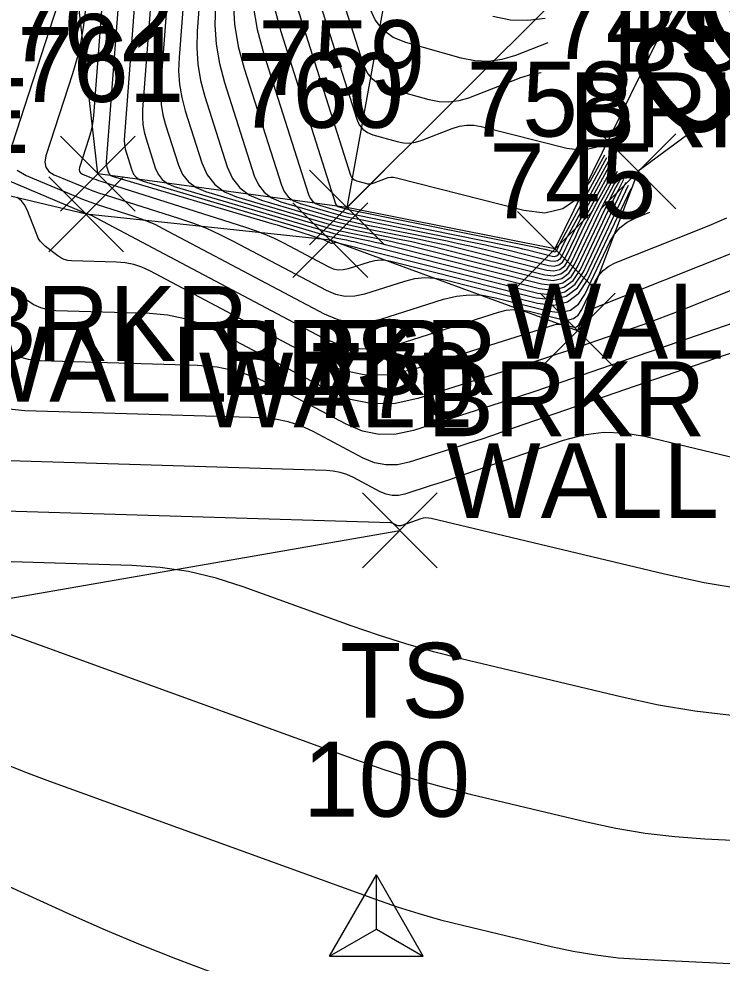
# Model space of a CAD drawing. Extents: x 1650836 to 1652450, y 332578 to 333908.
# Drawn here: x 1652071.34 to 1652090.12, y 332688.37 to 332713.58 of the extents above; entities that cross this region are included whole.
import ezdxf

# ---------------------------------------------------------------- set-up
doc = ezdxf.new("R2010")
doc.units = 0
for name, color, linetype in [('C_I', 7, 'Continuous'), ('CPSM', 7, 'Continuous'), ('L_A', 7, 'Continuous'), ('L_C', 7, 'Continuous'), ('L_I', 7, 'Continuous'), ('L_TIC', 7, 'Continuous'), ('LARO', 7, 'Continuous'), ('LAWE', 7, 'Continuous'), ('LELB', 7, 'Continuous'), ('LSOGCMA', 7, 'Continuous'), ('LSOGCMA_T', 7, 'Continuous'), ('LSOGCMI', 7, 'Continuous'), ('LW', 7, 'Continuous')]:
    doc.layers.add(name, color=color, linetype=linetype)

msp = doc.modelspace()

# ---------------------------------------------------------------- linework, layer by layer
at = {"layer": 'CPSM'}
for p, q in [((1652079.638, 332688.56), (1652080.888, 332690.725)), ((1652082.138, 332688.56), (1652080.888, 332690.725)), ((1652080.888, 332689.281), (1652080.888, 332690.725)), ((1652079.638, 332688.56), (1652080.888, 332689.281)), ((1652080.888, 332689.281), (1652080.888, 332689.281)), ((1652080.888, 332689.281), (1652082.138, 332688.56)), ((1652079.638, 332688.56), (1652082.138, 332688.56))]:
    msp.add_line(p, q, dxfattribs=at)
at = {"layer": 'L_TIC'}
for points in [[(1652072.451, 332708.446), (1652074.451, 332710.446)], [(1652074.451, 332708.446), (1652072.451, 332710.446)], [(1652086.881, 332708.509), (1652088.881, 332710.509)], [(1652088.881, 332708.509), (1652086.881, 332710.509)], [(1652079.101, 332707.542), (1652081.101, 332709.542)], [(1652081.101, 332707.542), (1652079.101, 332709.542)], [(1652079.101, 332707.542), (1652081.101, 332709.542)], [(1652081.101, 332707.542), (1652079.101, 332709.542)], [(1652079.101, 332707.542), (1652081.101, 332709.542)], [(1652081.101, 332707.542), (1652079.101, 332709.542)], [(1652072.141, 332707.362), (1652074.141, 332709.362)], [(1652074.141, 332707.362), (1652072.141, 332709.362)], [(1652078.661, 332706.671), (1652080.661, 332708.671)], [(1652080.661, 332706.671), (1652078.661, 332708.671)], [(1652084.656, 332706.437), (1652086.656, 332708.437)], [(1652086.656, 332706.437), (1652084.656, 332708.437)], [(1652085.261, 332704.252), (1652087.261, 332706.252)], [(1652087.261, 332704.252), (1652085.261, 332706.252)], [(1652080.514, 332698.922), (1652082.514, 332700.922)], [(1652082.514, 332698.922), (1652080.514, 332700.922)]]:
    msp.add_lwpolyline(points, dxfattribs=at)
at = {"layer": 'LARO'}
msp.add_lwpolyline([(1652076.603, 332758.368), (1652078.878, 332757.841), (1652083.698, 332755.279), (1652084.666, 332748.821), (1652086.861, 332729.205), (1652082.01, 332719.071), (1652080.101, 332708.542)], dxfattribs=at)
at = {"layer": 'LAWE'}
msp.add_lwpolyline([(1652113.729, 332729.971), (1652105.001, 332721.607), (1652097.708, 332720.127), (1652089.433, 332715.148), (1652085.656, 332707.437), (1652080.101, 332708.542), (1652073.451, 332709.446), (1652072.158, 332720.813), (1652060.852, 332721.144), (1652052.615, 332711.419), (1652043.802, 332704.554), (1652032.724, 332702.068), (1652025.188, 332702.458), (1652014.024, 332714.079), (1651995.915, 332712.612)], dxfattribs=at)
at = {"layer": 'LELB'}
for points in [[(1652083.698, 332755.279), (1652086.382, 332753.968), (1652097.265, 332747.108), (1652108.096, 332741.456), (1652107.571, 332735.708), (1652094.748, 332723.239), (1652088.748, 332717.173), (1652080.101, 332708.542)], [(1652062.736, 332702.235), (1652067.941, 332697.559), (1652081.514, 332699.922)]]:
    msp.add_lwpolyline(points, dxfattribs=at)
at = {"layer": 'LSOGCMA'}
for points in [[(1652076.593, 332713.944), (1652076.577, 332713.419), (1652076.613, 332712.9), (1652076.698, 332712.387), (1652076.834, 332711.88), (1652077.629, 332709.386), (1652077.737, 332709.144), (1652077.89, 332708.948), (1652078.089, 332708.799), (1652078.334, 332708.696), (1652079.404, 332708.38), (1652079.672, 332708.304), (1652079.942, 332708.234), (1652080.213, 332708.17), (1652080.486, 332708.111), (1652082.779, 332707.649), (1652083.083, 332707.585), (1652083.387, 332707.518), (1652083.69, 332707.448), (1652083.992, 332707.373), (1652085.485, 332706.996), (1652085.632, 332706.979), (1652085.756, 332707.009), (1652085.859, 332707.086), (1652085.94, 332707.21), (1652086.219, 332707.797), (1652086.289, 332707.943), (1652086.362, 332708.088), (1652086.437, 332708.233), (1652086.514, 332708.376), (1652087.215, 332709.661)], [(1652070.785, 332709.383), (1652073.122, 332708.394), (1652073.135, 332708.388), (1652073.147, 332708.384), (1652073.16, 332708.379), (1652073.173, 332708.375), (1652073.224, 332708.359), (1652073.237, 332708.354), (1652073.25, 332708.349), (1652073.262, 332708.344), (1652073.274, 332708.338), (1652079.442, 332705.071), (1652079.928, 332704.869), (1652080.423, 332704.771), (1652080.928, 332704.778), (1652081.442, 332704.89), (1652084.152, 332705.748), (1652084.354, 332705.798), (1652084.558, 332705.818), (1652084.763, 332705.81), (1652084.968, 332705.772), (1652085.813, 332705.559), (1652085.994, 332705.539), (1652086.149, 332705.576), (1652086.276, 332705.671), (1652086.376, 332705.824), (1652086.721, 332706.552), (1652086.82, 332706.72), (1652086.944, 332706.862), (1652087.094, 332706.976), (1652087.268, 332707.064), (1652089.414, 332707.92), (1652089.833, 332708.091), (1652090.249, 332708.267)], [(1652064.424, 332693.454), (1652072.723, 332689.668), (1652073.648, 332689.258), (1652074.581, 332688.866), (1652075.521, 332688.493), (1652076.47, 332688.139)]]:
    msp.add_lwpolyline(points, dxfattribs=at)
at = {"layer": 'LSOGCMI'}
for points in [[(1652073.978, 332719.42), (1652073.334, 332710.996), (1652073.318, 332710.84), (1652073.292, 332710.686), (1652073.257, 332710.534), (1652073.213, 332710.384), (1652072.962, 332709.612), (1652072.952, 332709.554), (1652072.962, 332709.506), (1652072.992, 332709.467), (1652073.043, 332709.436), (1652073.284, 332709.334), (1652073.344, 332709.309), (1652073.405, 332709.286), (1652073.467, 332709.264), (1652073.529, 332709.244), (1652077.394, 332708.022), (1652077.654, 332707.933), (1652077.909, 332707.833), (1652078.159, 332707.721), (1652078.405, 332707.598), (1652079.601, 332706.965), (1652079.733, 332706.91), (1652079.868, 332706.883), (1652080.005, 332706.885), (1652080.145, 332706.916), (1652080.709, 332707.094), (1652080.85, 332707.129), (1652080.992, 332707.143), (1652081.135, 332707.137), (1652081.278, 332707.111), (1652085.151, 332706.133), (1652085.584, 332706.084), (1652085.952, 332706.173), (1652086.256, 332706.4), (1652086.495, 332706.765), (1652087.622, 332709.139)], [(1652074.409, 332719.401), (1652073.673, 332709.765), (1652073.672, 332709.727), (1652073.675, 332709.691), (1652073.681, 332709.654), (1652073.69, 332709.618), (1652073.736, 332709.476), (1652073.751, 332709.443), (1652073.771, 332709.417), (1652073.798, 332709.397), (1652073.831, 332709.383), (1652078.099, 332708.12), (1652078.237, 332708.079), (1652078.375, 332708.037), (1652078.512, 332707.995), (1652078.65, 332707.952), (1652079.419, 332707.709), (1652079.447, 332707.699), (1652079.474, 332707.689), (1652079.5, 332707.677), (1652079.527, 332707.664), (1652079.654, 332707.596), (1652079.668, 332707.59), (1652079.683, 332707.587), (1652079.697, 332707.587), (1652079.712, 332707.591), (1652079.772, 332707.61), (1652079.788, 332707.613), (1652079.803, 332707.615), (1652079.818, 332707.614), (1652079.833, 332707.612), (1652085.198, 332706.256), (1652085.591, 332706.212), (1652085.924, 332706.292), (1652086.199, 332706.498), (1652086.415, 332706.829), (1652087.419, 332708.942), (1652087.478, 332709.064), (1652087.539, 332709.185), (1652087.557, 332709.221)], [(1652074.841, 332719.383), (1652074.16, 332710.461), (1652074.157, 332710.343), (1652074.164, 332710.226), (1652074.184, 332710.11), (1652074.214, 332709.995), (1652074.36, 332709.54), (1652074.406, 332709.436), (1652074.471, 332709.353), (1652074.557, 332709.289), (1652074.661, 332709.245), (1652079.576, 332707.791), (1652079.639, 332707.773), (1652079.703, 332707.757), (1652079.767, 332707.741), (1652079.831, 332707.728), (1652080.09, 332707.676), (1652080.154, 332707.662), (1652080.219, 332707.648), (1652080.283, 332707.633), (1652080.347, 332707.617), (1652085.246, 332706.379), (1652085.598, 332706.34), (1652085.896, 332706.412), (1652086.143, 332706.596), (1652086.336, 332706.892), (1652087.157, 332708.62), (1652087.249, 332708.811), (1652087.344, 332709.001), (1652087.442, 332709.19), (1652087.499, 332709.296)], [(1652075.273, 332719.364), (1652074.646, 332711.158), (1652074.641, 332710.958), (1652074.654, 332710.76), (1652074.687, 332710.565), (1652074.738, 332710.372), (1652074.983, 332709.605), (1652075.061, 332709.43), (1652075.171, 332709.288), (1652075.315, 332709.181), (1652075.492, 332709.107), (1652079.48, 332707.927), (1652079.615, 332707.889), (1652079.751, 332707.853), (1652079.888, 332707.821), (1652080.025, 332707.792), (1652080.577, 332707.68), (1652080.715, 332707.652), (1652080.852, 332707.621), (1652080.989, 332707.589), (1652081.126, 332707.556), (1652085.294, 332706.503), (1652085.604, 332706.468), (1652085.868, 332706.531), (1652086.086, 332706.694), (1652086.257, 332706.956), (1652086.895, 332708.299), (1652087.021, 332708.559), (1652087.15, 332708.818), (1652087.283, 332709.074), (1652087.42, 332709.329), (1652087.442, 332709.37)], [(1652075.705, 332719.345), (1652075.133, 332711.854), (1652075.125, 332711.573), (1652075.144, 332711.295), (1652075.189, 332711.021), (1652075.262, 332710.749), (1652075.607, 332709.669), (1652075.716, 332709.423), (1652075.872, 332709.224), (1652076.074, 332709.073), (1652076.322, 332708.969), (1652079.384, 332708.063), (1652079.591, 332708.004), (1652079.799, 332707.95), (1652080.009, 332707.901), (1652080.219, 332707.856), (1652081.064, 332707.685), (1652081.275, 332707.641), (1652081.486, 332707.595), (1652081.695, 332707.546), (1652081.905, 332707.494), (1652085.342, 332706.626), (1652085.611, 332706.596), (1652085.84, 332706.651), (1652086.029, 332706.792), (1652086.178, 332707.019), (1652086.69, 332708.099), (1652086.82, 332708.368), (1652086.954, 332708.635), (1652087.092, 332708.9), (1652087.233, 332709.163), (1652087.385, 332709.443)], [(1652076.137, 332719.326), (1652075.62, 332712.551), (1652075.609, 332712.188), (1652075.633, 332711.83), (1652075.692, 332711.476), (1652075.786, 332711.126), (1652076.23, 332709.734), (1652076.371, 332709.416), (1652076.572, 332709.16), (1652076.832, 332708.965), (1652077.153, 332708.831), (1652079.288, 332708.199), (1652079.567, 332708.12), (1652079.847, 332708.047), (1652080.13, 332707.98), (1652080.413, 332707.92), (1652081.552, 332707.69), (1652081.836, 332707.631), (1652082.119, 332707.568), (1652082.402, 332707.502), (1652082.684, 332707.433), (1652085.39, 332706.749), (1652085.618, 332706.723), (1652085.812, 332706.77), (1652085.972, 332706.89), (1652086.098, 332707.083), (1652086.533, 332707.998), (1652086.643, 332708.226), (1652086.757, 332708.453), (1652086.873, 332708.677), (1652086.993, 332708.901), (1652087.329, 332709.515)], [(1652076.569, 332719.307), (1652076.106, 332713.247), (1652076.093, 332712.804), (1652076.123, 332712.365), (1652076.195, 332711.932), (1652076.31, 332711.503), (1652076.906, 332709.633), (1652077.046, 332709.32), (1652077.244, 332709.067), (1652077.501, 332708.874), (1652077.817, 332708.742), (1652079.2, 332708.333), (1652079.547, 332708.234), (1652079.895, 332708.144), (1652080.246, 332708.061), (1652080.599, 332707.985), (1652082.039, 332707.695), (1652082.396, 332707.62), (1652082.753, 332707.542), (1652083.108, 332707.459), (1652083.463, 332707.371), (1652085.437, 332706.872), (1652085.625, 332706.851), (1652085.784, 332706.89), (1652085.916, 332706.988), (1652086.019, 332707.146), (1652086.376, 332707.898), (1652086.466, 332708.085), (1652086.559, 332708.271), (1652086.655, 332708.455), (1652086.753, 332708.638), (1652087.272, 332709.588)], [(1652085.29, 332712.134), (1652085.028, 332712.097), (1652084.739, 332712.008), (1652083.344, 332711.466), (1652083.086, 332711.388), (1652082.825, 332711.353), (1652082.563, 332711.362), (1652082.298, 332711.415), (1652081.235, 332711.715), (1652080.992, 332711.813), (1652080.794, 332711.959), (1652080.642, 332712.151), (1652080.535, 332712.391), (1652079.616, 332715.273)], [(1652079.188, 332714.594), (1652080.367, 332710.9), (1652080.432, 332710.753), (1652080.526, 332710.635), (1652080.647, 332710.546), (1652080.796, 332710.486), (1652081.447, 332710.302), (1652081.609, 332710.27), (1652081.77, 332710.264), (1652081.93, 332710.285), (1652082.088, 332710.333), (1652082.914, 332710.655), (1652083.105, 332710.713), (1652083.298, 332710.74), (1652083.493, 332710.737), (1652083.69, 332710.702), (1652085.969, 332710.123), (1652086.387, 332710.074), (1652086.748, 332710.154), (1652086.802, 332710.192)], [(1652072.374, 332713.955), (1652071.162, 332710.224)], [(1652077.062, 332714.034), (1652077.102, 332713.435), (1652077.201, 332712.842), (1652077.358, 332712.257), (1652078.352, 332709.139), (1652078.428, 332708.968), (1652078.537, 332708.829), (1652078.678, 332708.724), (1652078.851, 332708.651), (1652079.608, 332708.427), (1652079.798, 332708.373), (1652079.988, 332708.324), (1652080.18, 332708.278), (1652080.373, 332708.237), (1652083.583, 332707.589), (1652083.803, 332707.544), (1652084.021, 332707.496), (1652084.239, 332707.445), (1652084.457, 332707.391), (1652085.533, 332707.119), (1652085.639, 332707.107), (1652085.728, 332707.129), (1652085.802, 332707.184), (1652085.861, 332707.273), (1652086.061, 332707.696), (1652086.112, 332707.802), (1652086.165, 332707.906), (1652086.219, 332708.01), (1652086.274, 332708.113), (1652087.158, 332709.734)], [(1652077.592, 332713.97), (1652077.704, 332713.298), (1652077.881, 332712.634), (1652079.075, 332708.892), (1652079.12, 332708.792), (1652079.184, 332708.71), (1652079.266, 332708.648), (1652079.368, 332708.606), (1652079.812, 332708.475), (1652079.923, 332708.443), (1652080.035, 332708.414), (1652080.147, 332708.387), (1652080.261, 332708.363), (1652084.388, 332707.53), (1652084.522, 332707.502), (1652084.656, 332707.473), (1652084.789, 332707.442), (1652084.922, 332707.409), (1652085.581, 332707.242), (1652085.645, 332707.235), (1652085.7, 332707.249), (1652085.746, 332707.282), (1652085.781, 332707.337), (1652085.904, 332707.596), (1652085.935, 332707.66), (1652085.967, 332707.724), (1652086, 332707.788), (1652086.034, 332707.851), (1652087.102, 332709.807)], [(1652073.119, 332713.852), (1652073.072, 332713.409), (1652072.999, 332712.972), (1652072.9, 332712.539), (1652072.775, 332712.112), (1652072.062, 332709.918), (1652072.034, 332709.754), (1652072.062, 332709.616), (1652072.147, 332709.504), (1652072.29, 332709.419), (1652072.976, 332709.128), (1652073.148, 332709.058), (1652073.322, 332708.991), (1652073.497, 332708.929), (1652073.674, 332708.871), (1652075.602, 332708.261), (1652075.979, 332708.133), (1652076.349, 332707.987), (1652076.712, 332707.826), (1652077.068, 332707.647), (1652079.548, 332706.334), (1652079.798, 332706.229), (1652080.053, 332706.179), (1652080.313, 332706.183), (1652080.577, 332706.24), (1652081.645, 332706.579), (1652081.913, 332706.644), (1652082.182, 332706.671), (1652082.452, 332706.66), (1652082.723, 332706.611), (1652085.188, 332705.988), (1652085.623, 332705.939), (1652085.992, 332706.028), (1652086.297, 332706.256), (1652086.536, 332706.622), (1652087.69, 332709.051)], [(1652078.165, 332713.866), (1652078.333, 332713.237), (1652079.798, 332708.645), (1652079.811, 332708.615), (1652079.83, 332708.591), (1652079.855, 332708.573), (1652079.884, 332708.561), (1652080.016, 332708.522), (1652080.048, 332708.513), (1652080.081, 332708.504), (1652080.115, 332708.496), (1652080.148, 332708.489), (1652085.192, 332707.471), (1652085.241, 332707.461), (1652085.29, 332707.45), (1652085.339, 332707.439), (1652085.388, 332707.427), (1652085.629, 332707.366), (1652085.652, 332707.363), (1652085.672, 332707.368), (1652085.689, 332707.38), (1652085.702, 332707.4), (1652085.747, 332707.495), (1652085.758, 332707.519), (1652085.77, 332707.542), (1652085.782, 332707.565), (1652085.795, 332707.588), (1652087.045, 332709.88)], [(1652078.761, 332713.916), (1652080.199, 332709.409), (1652080.223, 332709.355), (1652080.257, 332709.311), (1652080.302, 332709.279), (1652080.356, 332709.256), (1652080.596, 332709.189), (1652080.655, 332709.177), (1652080.714, 332709.175), (1652080.773, 332709.183), (1652080.831, 332709.2), (1652081.135, 332709.318), (1652081.205, 332709.34), (1652081.276, 332709.35), (1652081.348, 332709.349), (1652081.421, 332709.336), (1652084.829, 332708.469), (1652085.384, 332708.404), (1652085.864, 332708.512), (1652086.27, 332708.79), (1652086.6, 332709.241), (1652086.988, 332709.953)], [(1652085.47, 332712.937), (1652084.601, 332712.599), (1652084.242, 332712.49), (1652083.881, 332712.442), (1652083.517, 332712.455), (1652083.149, 332712.528), (1652081.674, 332712.944), (1652081.337, 332713.081), (1652081.063, 332713.282), (1652080.852, 332713.55), (1652080.704, 332713.882)], [(1652085.399, 332713.592), (1652084.936, 332713.531), (1652084.47, 332713.548), (1652084, 332713.642)], [(1652071.302, 332709.542), (1652071.538, 332709.401), (1652072.853, 332708.844), (1652073.044, 332708.766), (1652073.236, 332708.692), (1652073.43, 332708.623), (1652073.626, 332708.559), (1652074.413, 332708.31), (1652074.608, 332708.243), (1652074.799, 332708.168), (1652074.987, 332708.085), (1652075.171, 332707.992), (1652079.495, 332705.702), (1652079.863, 332705.549), (1652080.238, 332705.475), (1652080.62, 332705.481), (1652081.01, 332705.565), (1652082.681, 332706.095), (1652083.025, 332706.179), (1652083.371, 332706.214), (1652083.718, 332706.199), (1652084.067, 332706.136), (1652085.5, 332705.773), (1652085.808, 332705.739), (1652086.071, 332705.802), (1652086.286, 332705.964), (1652086.456, 332706.223), (1652087.121, 332707.624), (1652087.244, 332707.833), (1652087.398, 332708.009), (1652087.583, 332708.151), (1652087.8, 332708.26), (1652088.186, 332708.414)], [(1652090.55, 332707.39), (1652086.566, 332705.8), (1652086.513, 332705.774), (1652086.468, 332705.739), (1652086.43, 332705.696), (1652086.4, 332705.645), (1652086.296, 332705.425), (1652086.265, 332705.379), (1652086.227, 332705.35), (1652086.18, 332705.338), (1652086.125, 332705.345), (1652085.87, 332705.409), (1652085.807, 332705.421), (1652085.745, 332705.423), (1652085.684, 332705.417), (1652085.622, 332705.402), (1652081.875, 332704.215), (1652081.236, 332704.076), (1652080.608, 332704.067), (1652079.993, 332704.188), (1652079.389, 332704.44), (1652074.837, 332706.851), (1652074.626, 332706.948), (1652074.409, 332707.019), (1652074.185, 332707.065), (1652073.954, 332707.085), (1652072.752, 332707.121), (1652072.652, 332707.132), (1652072.557, 332707.157), (1652072.468, 332707.197), (1652072.384, 332707.252), (1652072.057, 332707.502), (1652071.981, 332707.569), (1652071.916, 332707.644), (1652071.862, 332707.727), (1652071.819, 332707.819), (1652071.563, 332708.48), (1652071.497, 332708.612), (1652071.41, 332708.723), (1652071.302, 332708.813)], [(1652091.916, 332706.951), (1652089.017, 332705.794), (1652088.688, 332705.665), (1652088.358, 332705.54), (1652088.026, 332705.419), (1652087.693, 332705.302), (1652086.358, 332704.842), (1652086.024, 332704.728), (1652085.689, 332704.616), (1652085.354, 332704.506), (1652085.018, 332704.398), (1652081.997, 332703.442), (1652081.387, 332703.309), (1652080.788, 332703.3), (1652080.2, 332703.416), (1652079.624, 332703.656), (1652076.661, 332705.226), (1652076.224, 332705.427), (1652075.772, 332705.575), (1652075.307, 332705.669), (1652074.827, 332705.711), (1652072.334, 332705.787), (1652072.127, 332705.809), (1652071.93, 332705.862), (1652071.744, 332705.945), (1652071.569, 332706.059), (1652070.891, 332706.578)], [(1652091.725, 332705.909), (1652085.61, 332703.8), (1652085.146, 332703.642), (1652084.682, 332703.486), (1652084.216, 332703.334), (1652083.749, 332703.185), (1652081.88, 332702.593), (1652081.417, 332702.492), (1652080.963, 332702.486), (1652080.517, 332702.573), (1652080.08, 332702.756), (1652078.12, 332703.793), (1652077.642, 332704.014), (1652077.147, 332704.176), (1652076.638, 332704.279), (1652076.113, 332704.325), (1652071.916, 332704.453), (1652071.601, 332704.486), (1652071.302, 332704.566)], [(1652091.284, 332704.974), (1652084.308, 332702.568), (1652083.992, 332702.459), (1652083.675, 332702.354), (1652083.357, 332702.25), (1652083.039, 332702.148), (1652081.764, 332701.744), (1652081.448, 332701.675), (1652081.138, 332701.671), (1652080.834, 332701.731), (1652080.535, 332701.855), (1652079.199, 332702.563), (1652078.872, 332702.713), (1652078.535, 332702.824), (1652078.188, 332702.894), (1652077.83, 332702.925), (1652071.498, 332703.118), (1652071.075, 332703.163)], [(1652090.753, 332701.783), (1652088.048, 332702.431), (1652087.499, 332702.523), (1652086.955, 332702.536), (1652086.414, 332702.47), (1652085.878, 332702.325), (1652083.006, 332701.335), (1652082.837, 332701.277), (1652082.668, 332701.221), (1652082.498, 332701.165), (1652082.328, 332701.111), (1652081.647, 332700.895), (1652081.479, 332700.858), (1652081.313, 332700.856), (1652081.151, 332700.888), (1652080.991, 332700.954), (1652080.277, 332701.332), (1652080.103, 332701.413), (1652079.923, 332701.472), (1652079.737, 332701.509), (1652079.546, 332701.526), (1652071.08, 332701.784)], [(1652090.715, 332698.343), (1652089.642, 332698.522), (1652088.577, 332698.751), (1652082.348, 332700.242), (1652082.278, 332700.254), (1652082.208, 332700.256), (1652082.139, 332700.247), (1652082.071, 332700.229), (1652081.704, 332700.102), (1652081.683, 332700.095), (1652081.661, 332700.088), (1652081.639, 332700.081), (1652081.618, 332700.074), (1652081.531, 332700.046), (1652081.509, 332700.041), (1652081.488, 332700.041), (1652081.467, 332700.045), (1652081.447, 332700.054), (1652081.356, 332700.102), (1652081.334, 332700.112), (1652081.311, 332700.12), (1652081.287, 332700.125), (1652081.263, 332700.127), (1652070.662, 332700.45)], [(1652114.748, 332692.778), (1652113.236, 332693.516), (1652112.853, 332693.68), (1652112.46, 332693.803), (1652112.055, 332693.885), (1652111.641, 332693.926), (1652091.36, 332694.91), (1652090.372, 332694.981), (1652089.391, 332695.097), (1652088.417, 332695.26), (1652087.449, 332695.468), (1652083.154, 332696.496), (1652082.411, 332696.685), (1652081.674, 332696.895), (1652080.943, 332697.125), (1652080.219, 332697.376), (1652077.334, 332698.421), (1652076.607, 332698.652), (1652075.869, 332698.824), (1652075.119, 332698.937), (1652074.358, 332698.99), (1652070.244, 332699.115)], [(1652069.596, 332697.692), (1652080.331, 332693.804), (1652081.086, 332693.542), (1652081.848, 332693.302), (1652082.616, 332693.083), (1652083.39, 332692.886), (1652086.501, 332692.142), (1652087.282, 332691.974), (1652088.067, 332691.843), (1652088.858, 332691.749), (1652089.654, 332691.692), (1652105.571, 332690.92), (1652106.121, 332690.865), (1652106.656, 332690.757), (1652107.177, 332690.594), (1652107.684, 332690.377), (1652109.685, 332689.4), (1652110.187, 332689.214), (1652110.69, 332689.146), (1652111.196, 332689.195), (1652111.705, 332689.361), (1652129.142, 332697.063)], [(1652070.881, 332693.724), (1652071.521, 332693.47), (1652072.165, 332693.229), (1652080.865, 332690.078), (1652081.439, 332689.879), (1652082.018, 332689.697), (1652082.601, 332689.531), (1652083.19, 332689.381), (1652085.553, 332688.816), (1652086.146, 332688.688), (1652086.743, 332688.589), (1652087.344, 332688.517), (1652087.949, 332688.474), (1652099.502, 332687.913)]]:
    msp.add_lwpolyline(points, dxfattribs=at)
at = {"layer": 'LW'}
msp.add_lwpolyline([(1652113.729, 332729.971), (1652107.656, 332717.052), (1652097.986, 332712.237), (1652094.942, 332714.723), (1652087.881, 332709.509), (1652086.261, 332705.252), (1652079.661, 332707.671), (1652073.141, 332708.362), (1652066.208, 332710.013)], dxfattribs=at)

# ---------------------------------------------------------------- texts
at = {"layer": 'C_I'}
msp.add_text('100', height=2, dxfattribs=at).set_placement((1652078.928, 332692.281))
at = {"layer": 'L_A'}
for s, p in [('BS', (1652087.189, 332712.173)), ('BRKR', (1652086.023, 332710.148)), ('BRKR', (1652070.041, 332704.446)), ('WALL', (1652084.37, 332704.509)), ('BRKR', (1652076.691, 332703.542)), ('LER', (1652077.684, 332703.542)), ('BS', (1652078.542, 332703.542)), ('WALL', (1652069.629, 332703.362)), ('WALL', (1652076.149, 332702.671)), ('BRKR', (1652082.247, 332702.437)), ('WALL', (1652082.749, 332700.252)), ('TS', (1652079.923, 332694.922))]:
    msp.add_text(s, height=2, dxfattribs=at).set_placement(p)
at = {"layer": 'L_C'}
msp.add_text('S.SPRUCE', height=2, dxfattribs=at).set_placement((1652057.945, 332710.002))
at = {"layer": 'L_I'}
for s, p in [('762', (1652071.041, 332712.446)), ('744', (1652085.519, 332712.509)), ('759', (1652077.731, 332711.542)), ('759', (1652077.731, 332711.542)), ('759', (1652077.731, 332711.542)), ('761', (1652071.299, 332711.362)), ('760', (1652077.165, 332710.671)), ('758', (1652083.294, 332710.437)), ('745', (1652083.899, 332708.252)), ('770', (1652079.065, 332702.922))]:
    msp.add_text(s, height=2, dxfattribs=at).set_placement(p)
at = {"layer": 'LSOGCMA_T'}
msp.add_text('790', height=3, rotation=217.8949, dxfattribs=at).set_placement((1652092.564, 332716.557))

doc.saveas('drawing.dxf')
